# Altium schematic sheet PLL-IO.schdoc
size 302 x 215 mm; Symbol: Sheet_A4; Device: Sheet_A4; @Project Name: blueberry; REV: 1.0; Date: 2022-11-09; Sheet: 1/1; Draw By: aixiao@aixiao.me; @Page No: 2; @Page Count: 4; @Schematic Name: blueberry; @Board Name: blueberry; @Update Date: 2024-05-07; @Page Name: PLL-IO; @Create Time: 08:49:38; @Update Time: 11:45:56; @Create Date: 2023-10-26; SheetNumber: 2; SheetTotal: 4
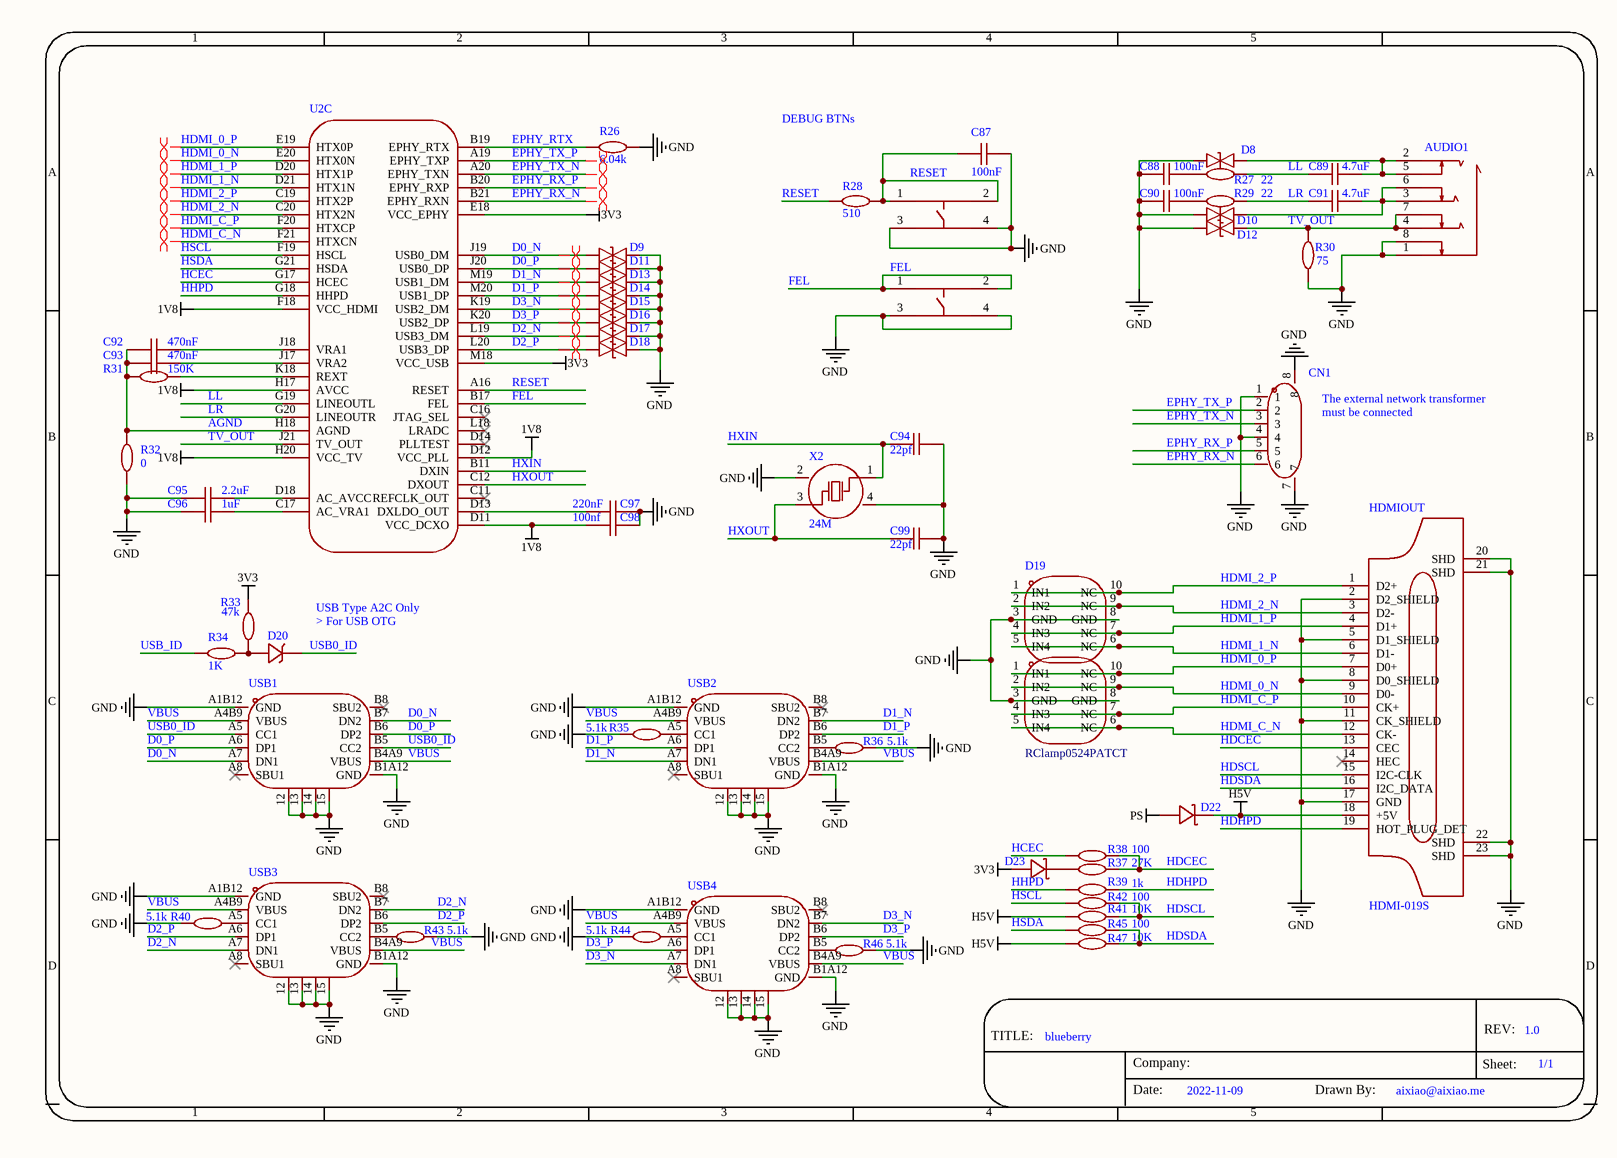
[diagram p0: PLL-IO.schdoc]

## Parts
AUDIO1  PJ-3930-8A  [AUDIO-TH_PJ-3930-8A]  (value not drawn)
C87  value 100nF  [C0402-NSK]  (hidden comment: FN15X104K250PNG)
C88  value 100nF  [C0402-NSK]  (hidden comment: CAP_0402)
C89  value 4.7uF  [C0402-NSK]  (hidden comment: CAP_0402)
C90  value 100nF  [C0402-NSK]  (hidden comment: CAP_0402)
C91  value 4.7uF  [C0402-NSK]  (hidden comment: CAP_0402)
C92  value 470nF  [C0402-NSK]  (hidden comment: CAP_0402)
C93  value 470nF  [C0402-NSK]  (hidden comment: CAP_0402)
C94  value 22pf  [C0402-NSK]  (hidden comment: CAP_0402)
C95  value 2.2uF  [C0402-NSK]  (hidden comment: CAP_0402)
C96  value 1uF  [C0402-NSK]  (hidden comment: CAP_0402)
C97  value 220nF  [C0402-NSK]  (hidden comment: CAP_0402)
C98  value 100nf  [C0402-NSK]  (hidden comment: CAP_0402)
C99  value 22pf  [C0402-NSK]  (hidden comment: CAP_0402)
CN1  532610671  [CONN-SMD_6P-P1.25_53261-0671]  (value not drawn)
D8  0402ESDA-05N  [D0402]  (value not drawn)
D9  0402ESDA-05N  [D0402]  (value not drawn)
D10  0402ESDA-05N  [D0402]  (value not drawn)
D11  0402ESDA-05N  [D0402]  (value not drawn)
D12  0402ESDA-05N  [D0402]  (value not drawn)
D13  0402ESDA-05N  [D0402]  (value not drawn)
D14  0402ESDA-05N  [D0402]  (value not drawn)
D15  0402ESDA-05N  [D0402]  (value not drawn)
D16  0402ESDA-05N  [D0402]  (value not drawn)
D17  0402ESDA-05N  [D0402]  (value not drawn)
D18  0402ESDA-05N  [D0402]  (value not drawn)
D19  RClamp0524PATCT  [SLP2510P8_L2.5-W1.0-P0.50-BL]
D20  1N5819-SOD523  [SOD-523_L1.2-W0.8-LS1.6-FD]  (value not drawn)
D21  RClamp0524PATCT  [SLP2510P8_L2.5-W1.0-P0.50-BL]  (value not drawn)
D22  B5819WS  [SOD-323_L1.8-W1.3-LS2.5-NSK]  (value not drawn)
D23  B5819WS  [SOD-323_L1.8-W1.3-LS2.5-NSK]  (value not drawn)
FEL  PTS810SJM250SMTRLFS  [KEY-SMD_4P-L4.2-W3.2-P2.20-LS4.6]  (value not drawn)
HDMIOUT  HDMI-019S  [HDMI-SMD_HDMI-019S]
R26  value 6.04k  [R0402-NSK_2]  (hidden comment: Res_0402)
R27  value 22  [R0402-NSK_2]  (hidden comment: Res_0402)
R28  value 510  [R0402-NSK_2]  (hidden comment: TR0402D10K0Q1025Z)
R29  value 22  [R0402-NSK_2]  (hidden comment: Res_0402)
R30  value 75  [R0402-NSK_2]  (hidden comment: Res_0402)
R31  value 150K  [R0402-NSK_2]  (hidden comment: Res_0402)
R32  value 0  [R0402-NSK_2]  (hidden comment: Res_0402)
R33  value 47k  [R0402-NSK_2]  (hidden comment: Res_0402)
R34  value 1K  [R0402-NSK_2]  (hidden comment: Res_0402)
R35  value 5.1k  [R0402-NSK_2]  (hidden comment: Res_0402)
R36  value 5.1k  [R0402-NSK_2]  (hidden comment: Res_0402)
R37  value 27K  [R0402-NSK_2]  (hidden comment: Res_0402)
R38  value 100  [R0402-NSK_2]  (hidden comment: Res_0402)
R39  value 1k  [R0402-NSK_2]  (hidden comment: Res_0402)
R40  value 5.1k  [R0402-NSK_2]  (hidden comment: Res_0402)
R41  value 10K  [R0402-NSK_2]  (hidden comment: Res_0402)
R42  value 100  [R0402-NSK_2]  (hidden comment: Res_0402)
R43  value 5.1k  [R0402-NSK_2]  (hidden comment: Res_0402)
R44  value 5.1k  [R0402-NSK_2]  (hidden comment: Res_0402)
R45  value 100  [R0402-NSK_2]  (hidden comment: Res_0402)
R46  value 5.1k  [R0402-NSK_2]  (hidden comment: Res_0402)
R47  value 10K  [R0402-NSK_2]  (hidden comment: Res_0402)
RESET  PTS810SJM250SMTRLFS  [KEY-SMD_4P-L4.2-W3.2-P2.20-LS4.6]  (value not drawn)
U2  Allwinner_H616  [BGA284P65B1200_1400H125]  (value not drawn)  (part C of 4)
USB1  TYPEC-304-BCP16  [USB-C-SMD_TYPEC-304-BCP16-1]  (value not drawn)
USB2  TYPEC-304-BCP16  [USB-C-SMD_TYPEC-304-BCP16-1]  (value not drawn)
USB3  TYPEC-304-BCP16  [USB-C-SMD_TYPEC-304-BCP16-1]  (value not drawn)
USB4  TYPEC-304-BCP16  [USB-C-SMD_TYPEC-304-BCP16-1]  (value not drawn)
X2  24M  [OSC-SMD_4P-L2.0-W1.6-BL]

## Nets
1V8: C98.1 U2.D11(VCC_DCXO) U2.D12(VCC_PLL) U2.F18(VCC_HDMI) U2.H17(AVCC) U2.H20(VCC_TV)
3V3: D23.2(A) R33.2 U2.E18(VCC_EPHY) U2.M18(VCC_USB)
GND: AUDIO1.1 AUDIO1.8 C87.2 C88.1 C90.1 C94.2 C95.1 C96.1 C97.2 C98.2 C99.2 CN1.1 CN1.4 CN1.7 CN1.8 D8.1 D9.2 D10.1 D11.2 D12.1 D13.2 D14.2 D15.2 D16.2 D17.2 D18.2 D19.3(GND) D19.8(GND) D21.3(GND) D21.8(GND) FEL.3 FEL.4 HDMIOUT.2(D2_SHIELD) HDMIOUT.5(D1_SHIELD) HDMIOUT.8(D0_SHIELD) HDMIOUT.11(CK_SHIELD) HDMIOUT.17(GND) HDMIOUT.20(SHD) HDMIOUT.21(SHD) HDMIOUT.22(SHD) HDMIOUT.23(SHD) R26.2 R30.1 R32.1 R35.1 R36.2 R40.1 R43.2 R44.1 R46.2 RESET.3 RESET.4 USB1.12 USB1.13 USB1.14 USB1.15 USB1.A1B12(GND) USB1.B1A12(GND) USB2.12 USB2.13 USB2.14 USB2.15 USB2.A1B12(GND) USB2.B1A12(GND) USB3.12 USB3.13 USB3.14 USB3.15 USB3.A1B12(GND) USB3.B1A12(GND) USB4.12 USB4.13 USB4.14 USB4.15 USB4.A1B12(GND) USB4.B1A12(GND) X2.2(GND) X2.4(GND)
H5V: D22.1(K) HDMIOUT.18(+5V) R41.1 R47.1
PS: D22.2(A)
AGND: C92.1 C93.1 R31.1 R32.2 U2.H18(AGND)
D0_N: D9.1 U2.J19(USB0_DM) USB1.A7(DN1) USB1.B7(DN2)
D0_P: D11.1 U2.J20(USB0_DP) USB1.A6(DP1) USB1.B6(DP2)
D1_N: D13.1 U2.M19(USB1_DM) USB2.A7(DN1) USB2.B7(DN2)
D1_P: D14.1 U2.M20(USB1_DP) USB2.A6(DP1) USB2.B6(DP2)
D2_N: D17.1 U2.L19(USB3_DM) USB3.A7(DN1) USB3.B7(DN2)
D2_P: D18.1 U2.L20(USB3_DP) USB3.A6(DP1) USB3.B6(DP2)
D3_N: D15.1 U2.K19(USB2_DM) USB4.A7(DN1) USB4.B7(DN2)
D3_P: D16.1 U2.K20(USB2_DP) USB4.A6(DP1) USB4.B6(DP2)
EPHY_RTX: R26.1 U2.B19(EPHY_RTX)
EPHY_RX_N: CN1.6 U2.B21(EPHY_RXN)
EPHY_RX_P: CN1.5 U2.B20(EPHY_RXP)
EPHY_TX_N: CN1.3 U2.A20(EPHY_TXN)
EPHY_TX_P: CN1.2 U2.A19(EPHY_TXP)
FEL: FEL.1 FEL.2 U2.B17(FEL)
HCEC: R38.1 U2.G17(HCEC)
HDCEC: HDMIOUT.13(CEC) R37.2 R38.2
HDHPD: HDMIOUT.19(HOT_PLUG_DET) R39.2
HDMI_0_N: D21.2(IN2) D21.9(NC) HDMIOUT.9(D0-) U2.E20(HTX0N)
HDMI_0_P: D21.1(IN1) D21.10(NC) HDMIOUT.7(D0+) U2.E19(HTX0P)
HDMI_1_N: D19.5(IN4) D19.6(NC) HDMIOUT.6(D1-) U2.D21(HTX1N)
HDMI_1_P: D19.4(IN3) D19.7(NC) HDMIOUT.4(D1+) U2.D20(HTX1P)
HDMI_2_N: D19.2(IN2) D19.9(NC) HDMIOUT.3(D2-) U2.C20(HTX2N)
HDMI_2_P: D19.1(IN1) D19.10(NC) HDMIOUT.1(D2+) U2.C19(HTX2P)
HDMI_C_N: D21.5(IN4) D21.6(NC) HDMIOUT.12(CK-) U2.F21(HTXCN)
HDMI_C_P: D21.4(IN3) D21.7(NC) HDMIOUT.10(CK+) U2.F20(HTXCP)
HDSCL: HDMIOUT.15(I2C-CLK) R41.2 R42.2
HDSDA: HDMIOUT.16(I2C_DATA) R45.2 R47.2
HHPD: R39.1 U2.G18(HHPD)
HSCL: R42.1 U2.F19(HSCL)
HSDA: R45.1 U2.G21(HSDA)
HXIN: C94.1 U2.B11(DXIN) X2.1(OSC1)
HXOUT: C99.1 U2.C12(DXOUT) X2.3(OSC2)
LL: C89.1 R27.2 U2.G19(LINEOUTL)
LR: C91.1 R29.2 U2.G20(LINEOUTR)
RESET: R28.1 U2.A16(RESET)
TV_OUT: AUDIO1.4 AUDIO1.7 D12.2 R30.2 U2.J21(TV_OUT)
USB0_ID: D20.2(K) USB1.A5(CC1) USB1.B5(CC2)
USB_ID: R34.1
VBUS: USB1.A4B9(VBUS) USB1.B4A9(VBUS) USB2.A4B9(VBUS) USB2.B4A9(VBUS) USB3.A4B9(VBUS) USB3.B4A9(VBUS) USB4.A4B9(VBUS) USB4.B4A9(VBUS)
NetAUDIO1_2: AUDIO1.2 AUDIO1.5 C89.2 D8.2
NetAUDIO1_3: AUDIO1.3 AUDIO1.6 C91.2 D10.2
NetC87_1: C87.1 R28.2 RESET.1 RESET.2
NetC88_2: C88.2 R27.1
NetC90_2: C90.2 R29.1
NetC92_2: C92.2 U2.J18(VRA1)
NetC93_2: C93.2 U2.J17(VRA2)
NetC95_2: C95.2 U2.D18(AC_AVCC)
NetC96_2: C96.2 U2.C17(AC_VRA1)
NetC97_1: C97.1 U2.D13(DXLDO_OUT)
NetD20_1: D20.1(A) R33.1 R34.2
NetD23_1: D23.1(K) R37.1
NetR31_2: R31.2 U2.K18(REXT)
NetR35_2: R35.2 USB2.A5(CC1)
NetR36_1: R36.1 USB2.B5(CC2)
NetR40_2: R40.2 USB3.A5(CC1)
NetR43_1: R43.1 USB3.B5(CC2)
NetR44_2: R44.2 USB4.A5(CC1)
NetR46_1: R46.1 USB4.B5(CC2)

Not connected (* = marked no-connect by the designer): HDMIOUT 14(HEC)*; U2 C11(REFCLK_OUT)* C16(JTAG_SEL)* D14(PLLTEST)* L18(LRADC)*; USB1 A8(SBU1)* B8(SBU2)*; USB2 A8(SBU1)* B8(SBU2)*; USB3 A8(SBU1)* B8(SBU2)*; USB4 A8(SBU1)* B8(SBU2)*

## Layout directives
differential pair: D0_N, D0_P, D1_N, D1_P, D2_N, D2_P, D3_N, D3_P, EPHY_RX_N, EPHY_RX_P, EPHY_TX_N, EPHY_TX_P, HDMI_0_N, HDMI_0_P, HDMI_1_N, HDMI_1_P, HDMI_2_N, HDMI_2_P, HDMI_C_N, HDMI_C_P

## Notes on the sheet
- DEBUG BTNs
- The external network transformer
  must be connected
- (near USB1) USB Type A2C Only
  > For USB OTG

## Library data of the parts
AUDIO1 = PJ-3930-8A: Manufacturer: 韩国韩荣; Add into BOM: yes; Connector Type: 3.5mm耳机座; Current Rating (Max): 500mA; Voltage Rating (Max): 30V
C87 = FN15X104K250PNG: Manufacturer: PSA(信昌电陶); Add into BOM: yes; Tolerance: ±10%; Voltage Rated: 25V; Temperature Coefficient: X7R
C88-C99 = CAP_0402: Symbol: C1210X7R475K630NT; Convert to PCB: yes
CN1 = 532610671: Manufacturer: MOLEX; Symbol: 53261-0671; Add into BOM: yes; Pitch: 1.25mm; Pins Structure: 1x6P; Number of PINs Per Row: 6
D8-D18 = 0402ESDA-05N: Manufacturer: BORN伯恩半导体; Add into BOM: yes; Polarity: Bidirectional; Voltage - Reverse Standoff (Typ): 5V; Voltage - Clamping (Max) @ Ipp: 50V
D19 D21 = RClamp0524PATCT: Manufacturer: SEMTECH; Add into BOM: yes
D20 = 1N5819-SOD523: Add into BOM: yes
D22 D23 = B5819WS: Manufacturer: CJ（江苏长电/长晶）; Symbol: B5819WS_C22624; Add into BOM: yes; Reverse Voltage (Vr): 40V; Average Rectified Current (Io): 1A; Forward Voltage (Vf@If): 600mV@1A
FEL RESET = PTS810SJM250SMTRLFS: Manufacturer: C&K; Add into BOM: yes; Contact Current: 50mA; Voltage Rating (DC): 16V; Circuit: 单刀单掷; Actuator Style: 圆形按钮; Operating Force: 160gf; Pin Style: J型引脚; Switch Length: 4.2mm; Switch Width: 3.2mm; Switch Height: 2.5mm
HDMIOUT = HDMI-019S: Manufacturer: SOFNG(硕方); Add into BOM: yes; Connector Type: HDMI; Gender: 母; Current Rating (Max): 500mA
R26 R27 R29-R47 = Res_0402: Symbol: 电阻; Convert to PCB: yes
R28 = TR0402D10K0Q1025Z: Manufacturer: EVER OHMS(天二科技); Symbol: TR0402D10KQ1025; Add into BOM: yes; Tolerance: ±0.5%; Power(Watts): 63mW; Temperature Coefficient: ±25ppm/; Overload Voltage (Max): 25V
U2 = Allwinner_H616: Symbol: H616-BGA-190823; Convert to PCB: yes
USB1-USB4 = TYPEC-304-BCP16: Manufacturer: XUNPU; Pin Type: IN; Add into BOM: yes
X2 = SX32Y024000BC1T: Manufacturer: TKD(泰晶); Add into BOM: yes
